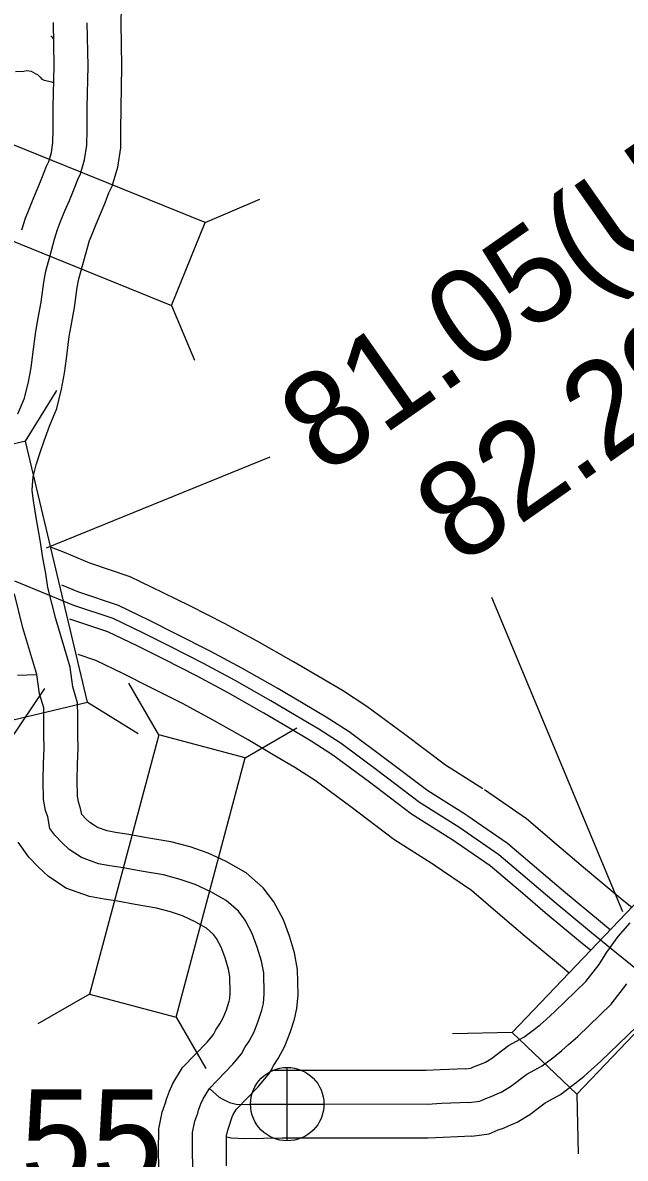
# Model space of a CAD drawing. Extents: x 31699 to 244310, y -8841 to 11474.
# Drawn here: x 96550.4 to 96728.2, y 4260.7 to 4595.9 of the extents above; entities that cross this region are included whole.
import ezdxf

# ---------------------------------------------------------------- set-up
doc = ezdxf.new("R2010")
doc.units = 0
for name, color, linetype in [('B_Logo', 7, 'Continuous'), ('Level 21', 7, 'Continuous'), ('New Level (0)', 7, 'Continuous'), ('R_Draft', 7, 'Continuous'), ('R_XS_EARTHWORK_STAGE1', 7, 'Continuous'), ('R_XS_EARTHWORK_STAGE2', 7, 'Continuous'), ('S_WALL', 7, 'Continuous')]:
    doc.layers.add(name, color=color, linetype=linetype)

msp = doc.modelspace()

# ---------------------------------------------------------------- linework, layer by layer
at = {"layer": 'B_Logo'}
for points in [[(96549, 4480.46), (96550.92, 4485.1), (96552.1, 4489.92), (96552.9, 4494), (96553.43, 4498.08), (96554.26, 4504.71), (96554.87, 4508.19), (96555.85, 4513.41), (96556.62, 4519.36), (96557.23, 4522.57), (96558.48, 4527.2), (96559.8, 4531.96), (96560.69, 4534.91), (96561.58, 4537.19), (96562.86, 4540.35), (96564.21, 4543.38), (96565.43, 4546.33), (96566.64, 4549.62), (96567.48, 4551.31), (96568.68, 4555.4), (96569.34, 4559.75), (96569.4, 4564.29), (96569.42, 4570.89), (96569.69, 4583.11), (96569.48, 4595.92)], [(96679.09, 4358.42), (96667.52, 4365.73), (96655.19, 4375.07), (96644.34, 4383.1), (96637.74, 4387.4), (96631.08, 4391.29), (96623.62, 4395.71), (96613.07, 4401.68), (96603.8, 4406.73), (96593.93, 4411.71), (96586.01, 4415.65), (96577.08, 4419.98), (96565.5, 4423.86), (96557.66, 4427.14), (96548.07, 4431.05)], [(96605.52, 4281.29), (96612.4, 4288.41), (96614.94, 4291.52), (96615.98, 4293.34), (96617.21, 4295.23), (96618.7, 4297.99), (96619.91, 4301.14), (96620.99, 4304.36), (96621.42, 4306.37), (96621.64, 4309.25), (96621.54, 4315.39), (96620.89, 4318.91), (96619.62, 4323.03), (96618.16, 4327.01), (96616.09, 4330.98), (96614.05, 4333.62), (96610.47, 4336.76), (96605.9, 4339.36), (96601.34, 4341.49), (96596.92, 4343.02), (96591.97, 4344.34), (96585.36, 4345.43), (96580.02, 4346.41), (96576.15, 4347.02), (96572.74, 4347.63), (96567.79, 4349.42), (96565.83, 4350.79), (96564.15, 4351.83), (96562.06, 4353.79), (96559.89, 4356.03), (96558.46, 4358.01), (96557.8, 4361.47), (96557.17, 4363.39), (96556.59, 4366.59), (96556.49, 4372.26), (96556.55, 4377.26), (96556.74, 4381.74), (96556.68, 4385.54), (96556.65, 4391.28), (96556.61, 4393.62), (96555.41, 4397.74), (96554.58, 4403.53), (96550.5, 4417.28), (96548, 4427.32)], [(96548.86, 4403.3), (96554.58, 4403.53)], [(96734.84, 4313.75), (96725.56, 4321.18), (96718.22, 4327.22), (96707.26, 4336.36), (96700.66, 4342.01), (96690.91, 4350.3), (96679.09, 4358.42)], [(96682.06, 4277.14), (96685.32, 4277.58), (96687.04, 4278.34), (96688.63, 4278.89), (96689.75, 4279.37), (96691.61, 4280.2), (96694.38, 4281.91), (96699.13, 4285.51), (96703.69, 4287.97), (96707.18, 4290.62), (96709.49, 4292.45), (96711.46, 4294.22), (96714.22, 4296.66), (96724.02, 4306.13), (96728.67, 4312.14)], [(96600.57, 4258.18), (96600.5, 4262.78), (96600.54, 4268.32), (96601.22, 4271.61), (96602.05, 4274.02), (96602.3, 4274.89), (96603, 4276.71), (96603.64, 4278.19), (96605.52, 4281.29)], [(96682.06, 4277.14), (96674.04, 4276.8), (96669.72, 4276.59), (96626.9, 4276.63), (96616.05, 4276.45), (96613.39, 4276.54), (96611.78, 4276.98), (96610.98, 4277.3), (96609.37, 4278.08), (96608.43, 4278.66), (96605.52, 4281.29)]]:
    msp.add_lwpolyline(points, dxfattribs=at)
at = {"layer": 'Level 21'}
for p, q in [((96628.46, 4265.81), (96628.46, 4287.48)), ((96617.63, 4276.65), (96639.29, 4276.65))]:
    msp.add_line(p, q, dxfattribs=at)
msp.add_circle((96628.46, 4276.65), 10.83, dxfattribs=at)
at = {"layer": 'New Level (0)'}
for points in [[(96686.21, 4369.69), (96675.12, 4376.7), (96663.18, 4385.74), (96651.95, 4394.05), (96644.75, 4398.74), (96637.85, 4402.78), (96630.3, 4407.25), (96619.55, 4413.34), (96610, 4418.54), (96599.9, 4423.63), (96591.89, 4427.62), (96582.13, 4432.35), (96570.2, 4436.35), (96562.75, 4439.46), (96558.95, 4441.01)], [(96681.31, 4361.94), (96669.9, 4369.15), (96657.68, 4378.4), (96646.71, 4386.52), (96639.93, 4390.94), (96633.2, 4394.89), (96625.71, 4399.32), (96615.09, 4405.32), (96605.74, 4410.42), (96595.8, 4415.44), (96587.85, 4419.39), (96578.66, 4423.85), (96566.97, 4427.77), (96561.93, 4429.87)], [(96676.86, 4354.9), (96665.15, 4362.3), (96652.69, 4371.73), (96641.96, 4379.68), (96635.55, 4383.85), (96628.97, 4387.7), (96621.54, 4392.1), (96611.05, 4398.04), (96601.86, 4403.04), (96592.07, 4407.99), (96584.17, 4411.91), (96575.51, 4416.11), (96564.37, 4419.85)], [(96671.97, 4347.15), (96659.92, 4354.75), (96647.19, 4364.4), (96636.72, 4372.15), (96630.73, 4376.05), (96624.32, 4379.8), (96616.94, 4384.17), (96606.6, 4390.02), (96597.61, 4394.93), (96587.96, 4399.79), (96580.13, 4403.69), (96572.04, 4407.61), (96566.78, 4409.37)], [(96730.18, 4334.65), (96726.73, 4337.49), (96715.87, 4346.54), (96709.32, 4352.16), (96699.02, 4360.9), (96686.64, 4369.41)], [(96723.81, 4328.02), (96720.88, 4330.43), (96709.95, 4339.54), (96703.37, 4345.18), (96693.44, 4353.61), (96681.45, 4361.86)], [(96717.89, 4322.09), (96715.57, 4324.01), (96704.57, 4333.18), (96697.96, 4338.84), (96688.37, 4346.98), (96676.73, 4354.99)], [(96711.67, 4315.35), (96709.72, 4316.96), (96698.65, 4326.18), (96692.01, 4331.87), (96682.79, 4339.69), (96671.53, 4347.43)]]:
    msp.add_lwpolyline(points, dxfattribs=at)
at = {"layer": 'R_Draft'}
for points in [[(96558.67, 4592.02), (96559.09, 4591.62), (96559.5, 4591.09), (96559.53, 4591.06)], [(96548.27, 4581.49), (96550.8, 4581.6), (96551.66, 4581.82), (96552.87, 4581.57), (96553.61, 4581.18), (96554.34, 4580.86), (96554.75, 4580.6), (96555.56, 4579.88), (96556.1, 4579.29), (96556.77, 4578.96), (96558.11, 4578.65), (96558.91, 4578.46), (96559.48, 4578.27)]]:
    msp.add_lwpolyline(points, dxfattribs=at)
at = {"layer": 'R_XS_EARTHWORK_STAGE1'}
for p, q in [((96604.21, 4536.94), (96620.42, 4543.8)), ((96594.29, 4512.47), (96601.15, 4496.26)), ((96551.23, 4472.35), (96560.47, 4487.33)), ((96590.58, 4385.7), (96581.77, 4400.93)), ((96569.51, 4395.29), (96584.49, 4386.05)), ((96616.09, 4378.89), (96631.32, 4387.7)), ((96570.15, 4309.17), (96554.92, 4300.36)), ((96595.66, 4302.37), (96604.48, 4287.13)), ((96694.82, 4297.8), (96677.23, 4297.39)), ((96713.92, 4279.58), (96714.34, 4261.98))]:
    msp.add_line(p, q, dxfattribs=at)
for points in [[(96520.89, 4542.22), (96594.29, 4512.47), (96604.21, 4536.94), (96530.81, 4566.69)], [(96525.54, 4466.26), (96543.82, 4389.19), (96569.51, 4395.29), (96551.23, 4472.35)], [(96595.66, 4302.37), (96616.09, 4378.89), (96590.58, 4385.7), (96570.15, 4309.17)], [(96749.49, 4355.11), (96694.82, 4297.8), (96713.92, 4279.58), (96768.59, 4336.88)]]:
    msp.add_lwpolyline(points, close=True, dxfattribs=at)
at = {"layer": 'R_XS_EARTHWORK_STAGE2'}
for points in [[(96613.49, 4275.15), (96619.88, 4281.76), (96623.22, 4285.84), (96624.52, 4288.12), (96625.82, 4290.11), (96627.8, 4293.81), (96629.32, 4297.76), (96630.65, 4301.71), (96631.34, 4304.93), (96631.65, 4308.95), (96631.53, 4316.39), (96630.61, 4321.31), (96629.1, 4326.23), (96627.32, 4331.06), (96624.55, 4336.39), (96621.37, 4340.5), (96616.3, 4344.95), (96610.49, 4348.25), (96605.1, 4350.77), (96599.85, 4352.58), (96594.08, 4354.12), (96587.08, 4355.28), (96581.69, 4356.27), (96577.8, 4356.88), (96575.34, 4357.32), (96572.44, 4358.37), (96571.34, 4359.14), (96570.27, 4359.8), (96569.07, 4360.93), (96567.84, 4362.19), (96567.51, 4363.97), (96566.89, 4365.86), (96566.57, 4367.58), (96566.49, 4372.29), (96566.54, 4377), (96566.74, 4381.61), (96566.68, 4385.65), (96566.65, 4391.39), (96566.59, 4395.12), (96565.21, 4399.85), (96564.38, 4405.67), (96560.15, 4419.91), (96557.84, 4429.21), (96557.27, 4433.35), (96556.38, 4437.9), (96555.56, 4443.12), (96555.04, 4445.92), (96554.47, 4449.26), (96553.98, 4452.29), (96553.55, 4455.4), (96553.25, 4457.95), (96553.27, 4459.39), (96553.55, 4461.85), (96554.38, 4465.4), (96555.56, 4468.99), (96556.72, 4472.46), (96558.31, 4476.82), (96560.45, 4481.97), (96561.87, 4487.77), (96562.78, 4492.4), (96563.35, 4496.82), (96564.15, 4503.23), (96564.71, 4506.4), (96565.73, 4511.84), (96566.49, 4517.78), (96566.98, 4520.32), (96568.13, 4524.55), (96569.41, 4529.19), (96570.15, 4531.65), (96570.87, 4533.49), (96572.07, 4536.44), (96573.4, 4539.44), (96574.75, 4542.7), (96575.83, 4545.66), (96576.82, 4547.64), (96578.46, 4553.23), (96579.33, 4558.93), (96579.39, 4564.2), (96579.42, 4570.77), (96579.69, 4583.08), (96579.48, 4595.89), (96579.97, 4618.27)], [(96550.2, 4534.73), (96551.23, 4538.17), (96552.29, 4540.9), (96553.66, 4544.27), (96555.02, 4547.32), (96556.11, 4549.97), (96557.44, 4553.59), (96558.13, 4554.97), (96558.89, 4557.56), (96559.35, 4560.57), (96559.4, 4564.37), (96559.42, 4571.02), (96559.68, 4583.14), (96559.47, 4595.95)], [(96597.55, 4287.43), (96604.92, 4295.06), (96606.67, 4297.2), (96607.44, 4298.55), (96608.61, 4300.34), (96609.59, 4302.17), (96610.5, 4304.53), (96611.33, 4307.01), (96611.5, 4307.81), (96611.64, 4309.55), (96611.56, 4314.38), (96611.16, 4316.52), (96610.14, 4319.83), (96608.99, 4322.96), (96607.63, 4325.57), (96606.73, 4326.74), (96604.64, 4328.57), (96601.31, 4330.47), (96597.58, 4332.21), (96593.99, 4333.45), (96589.86, 4334.55), (96583.64, 4335.58), (96578.35, 4336.55), (96574.49, 4337.15), (96570.14, 4337.94), (96563.14, 4340.46), (96560.33, 4342.43), (96558.04, 4343.85), (96555.04, 4346.66), (96552.21, 4349.58), (96549.05, 4353.96)], [(96681.17, 4287.11), (96682.58, 4287.3), (96683.37, 4287.65), (96685.01, 4288.22), (96685.75, 4288.54), (96686.93, 4289.06), (96688.73, 4290.17), (96693.7, 4293.94), (96698.26, 4296.4), (96701.05, 4298.52), (96703.04, 4300.1), (96704.82, 4301.69), (96707.44, 4304), (96716.55, 4312.82), (96720.46, 4317.87), (96722.76, 4321.53), (96726.05, 4326.18), (96729.62, 4330.2)], [(96682.95, 4267.16), (96688.06, 4267.86), (96690.71, 4269.03), (96692.25, 4269.56), (96693.76, 4270.21), (96696.28, 4271.33), (96700.04, 4273.64), (96704.56, 4277.07), (96709.12, 4279.54), (96713.31, 4282.72), (96715.93, 4284.8), (96718.1, 4286.74), (96721.01, 4289.31), (96731.49, 4299.44)], [(96590.58, 4257.96), (96590.5, 4262.74), (96590.55, 4269.39), (96591.55, 4274.25), (96592.51, 4277.03), (96592.81, 4278.1), (96593.75, 4280.51), (96594.74, 4282.79), (96597.55, 4287.43)], [(96681.17, 4287.11), (96673.59, 4286.79), (96669.48, 4286.59), (96626.83, 4286.63), (96623.7, 4286.58)], [(96610.57, 4258.4), (96610.5, 4262.83), (96610.53, 4267.26), (96610.89, 4268.97), (96611.59, 4271.01), (96611.78, 4271.69), (96612.25, 4272.91), (96612.55, 4273.58), (96613.49, 4275.15)], [(96682.95, 4267.16), (96674.49, 4266.81), (96669.95, 4266.59), (96626.98, 4266.63), (96615.97, 4266.45), (96611.88, 4266.59), (96610.57, 4266.95)]]:
    msp.add_lwpolyline(points, dxfattribs=at)
at = {"layer": 'S_WALL'}
for p, q in [((96623.29, 4467.64), (96557.33, 4440.83)), ((96688.73, 4426.35), (96727.34, 4333.56)), ((96522.35, 4348), (96556.92, 4399.4))]:
    msp.add_line(p, q, dxfattribs=at)

# ---------------------------------------------------------------- texts
for s, p in [('81.05(U.P.)', (96639.53, 4461.9)), ('82.29(U.P.)', (96679.54, 4435.27))]:
    msp.add_text(s, height=28.1599, rotation=35, dxfattribs=at).set_placement(p)
msp.add_text('1.55', height=28.16, dxfattribs=at).set_placement((96518.44, 4252.85))

doc.saveas('drawing.dxf')
